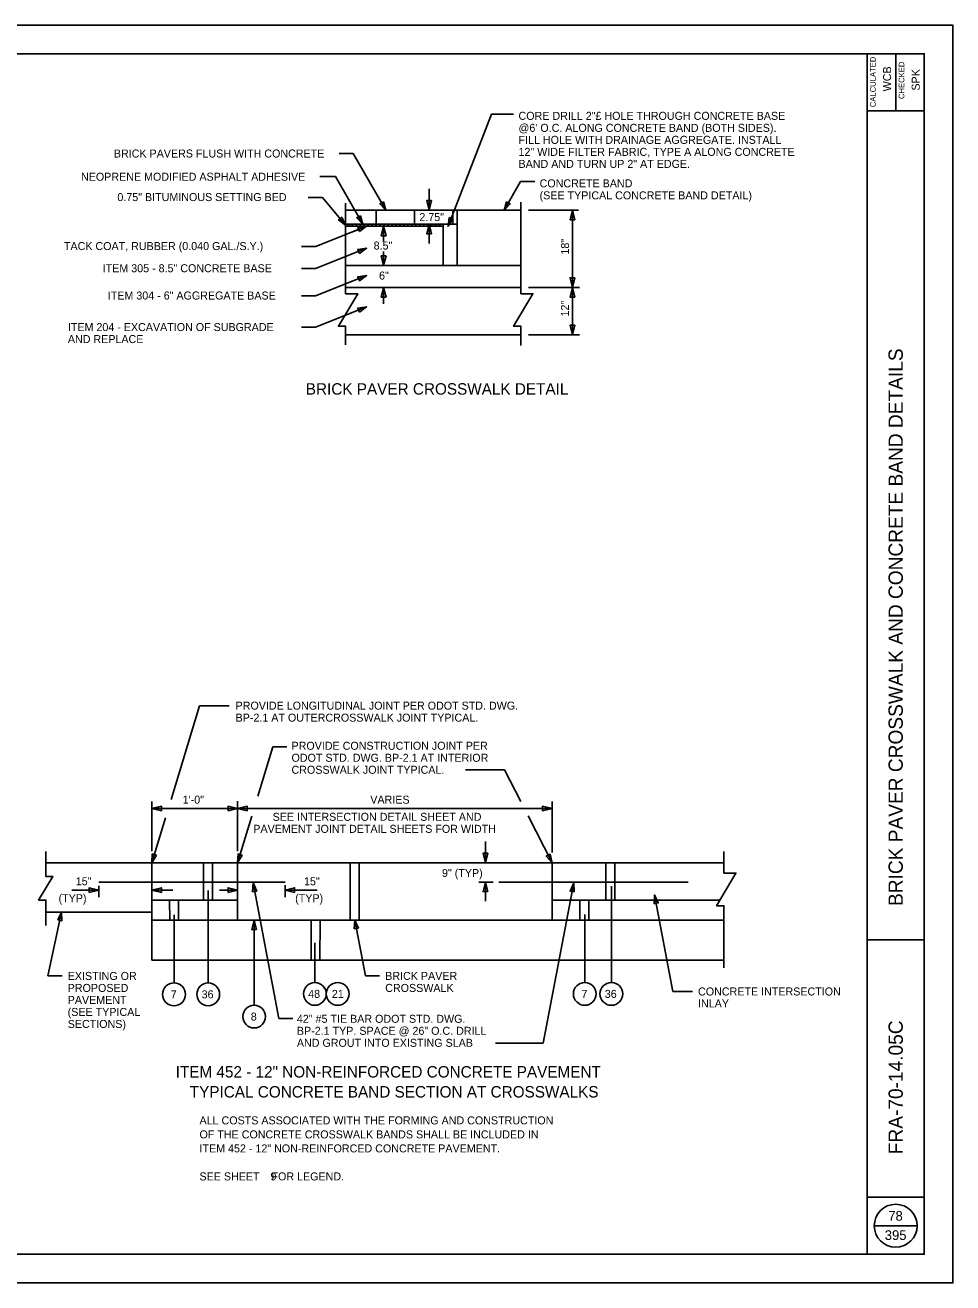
# Model space of a CAD drawing. Extents: x -848 to 1, y -1131 to -115.
# Drawn here: x -351.5 to -189.3, y -1130.8 to -910.8 of the extents above; entities that cross this region are included whole.
import ezdxf

# ---------------------------------------------------------------- set-up
doc = ezdxf.new("R2010")
doc.units = 0
for name, color, linetype in [('SH_Border', 7, 'Continuous'), ('SH_Cut_Line', 7, 'Continuous'), ('SH_Data', 7, 'Continuous'), ('SH_Text', 7, 'Continuous'), ('TX_X_5', 7, 'Continuous')]:
    doc.layers.add(name, color=color, linetype=linetype)

msp = doc.modelspace()

# ---------------------------------------------------------------- linework, layer by layer
at = {"layer": 'SH_Border'}
for p, q in [((-204.28, -1125.76), (-204.28, -915.76)), ((-199.28, -915.76), (-199.28, -925.76)), ((-204.28, -925.76), (-194.28, -925.76)), ((-204.28, -1070.76), (-194.28, -1070.76)), ((-204.28, -1115.76), (-194.28, -1115.76))]:
    msp.add_line(p, q, dxfattribs=at)
msp.add_lwpolyline([(-509.28, -915.76), (-194.28, -915.76), (-194.28, -1125.76), (-509.28, -1125.76)], close=True, dxfattribs=at)
at = {"layer": 'SH_Cut_Line'}
msp.add_lwpolyline([(-529.28, -1130.76), (-189.28, -1130.76), (-189.28, -910.76), (-529.28, -910.76)], close=True, dxfattribs=at)
at = {"layer": 'SH_Data'}
for p, q in [((-295.47, -943.13), (-264.82, -943.13)), ((-290.16, -943.13), (-290.16, -945.57)), ((-283.45, -943.13), (-283.45, -945.57)), ((-276.74, -943.13), (-276.74, -945.57)), ((-275.99, -943.13), (-275.99, -952.81)), ((-295.47, -945.57), (-275.99, -945.57)), ((-295.47, -945.92), (-295.47, -947.39)), ((-291.8, -945.92), (-293.05, -946.83)), ((-291.63, -945.92), (-291.8, -945.92)), ((-288.86, -945.92), (-289.55, -945.92)), ((-289.25, -947.6), (-288.83, -945.92)), ((-288.83, -945.92), (-288.86, -945.92)), ((-288.17, -945.92), (-288.83, -945.92)), ((-287.48, -945.92), (-288.17, -945.92)), ((-281.94, -945.92), (-282.63, -945.92)), ((-281.25, -945.92), (-281.94, -945.92)), ((-280.56, -945.92), (-281.25, -945.92)), ((-278.43, -945.92), (-278.59, -945.92)), ((-278.43, -948.01), (-278.43, -945.92)), ((-275.99, -952.81), (-275.99, -945.57)), ((-293.19, -946.48), (-295.47, -947.39)), ((-295.47, -947.39), (-293.19, -946.48)), ((-295.47, -947.39), (-295.47, -951.24)), ((-293.05, -946.83), (-293.19, -946.48)), ((-278.43, -949.37), (-278.43, -948.01)), ((-293.21, -950.33), (-293.35, -949.98)), ((-293.07, -950.68), (-293.21, -950.33)), ((-295.47, -951.24), (-295.47, -952.81)), ((-288.83, -952.81), (-289.25, -951.13)), ((-289.25, -951.13), (-288.83, -951.13)), ((-288.83, -951.13), (-288.41, -951.13)), ((-288.41, -951.13), (-288.83, -952.81)), ((-278.43, -952.81), (-278.43, -950.79)), ((-278.43, -950.79), (-278.43, -952.81)), ((-295.47, -952.81), (-264.82, -952.81)), ((-288.83, -952.81), (-295.47, -952.81)), ((-295.47, -952.81), (-295.47, -956.02)), ((-295.47, -952.81), (-288.83, -952.81)), ((-275.99, -952.81), (-288.83, -952.81)), ((-288.83, -952.81), (-278.43, -952.81)), ((-278.43, -952.81), (-275.99, -952.81)), ((-264.82, -952.81), (-275.99, -952.81)), ((-264.82, -956.63), (-264.82, -952.81)), ((-295.47, -956.02), (-295.47, -956.63)), ((-295.47, -956.63), (-264.82, -956.63)), ((-295.47, -964.93), (-264.82, -964.93)), ((-347.88, -1057.29), (-329.36, -1057.29)), ((-329.36, -1057.29), (-329.36, -1074.29)), ((-329.36, -1057.29), (-229.33, -1057.29)), ((-314.36, -1057.29), (-314.36, -1067.29)), ((-259.36, -1057.29), (-259.36, -1067.29)), ((-338.62, -1060.64), (-306.07, -1060.64)), ((-268.68, -1060.64), (-235.57, -1060.64)), ((-329.36, -1063.84), (-314.36, -1063.84)), ((-259.36, -1063.84), (-230.04, -1063.84)), ((-347.88, -1065.89), (-329.36, -1065.89)), ((-329.36, -1067.29), (-244.36, -1067.29)), ((-244.36, -1067.29), (-229.33, -1067.29)), ((-329.36, -1074.29), (-229.33, -1074.29)), ((-203.03, -1120.76), (-195.53, -1120.76))]:
    msp.add_line(p, q, dxfattribs=at)
for points in [[(-295.47, -941.91), (-295.47, -957.73), (-293.37, -957.73), (-296.75, -963.44), (-295.47, -963.44), (-295.47, -966.67)], [(-295.47, -941.91), (-295.47, -957.73), (-293.37, -957.73), (-296.75, -963.44), (-295.47, -963.44), (-295.47, -966.67)], [(-264.82, -941.7), (-264.82, -957.73), (-262.72, -957.73), (-266.09, -963.44), (-264.82, -963.44), (-264.82, -966.77)], [(-291.8, -945.92), (-292.32, -945.92), (-293.01, -945.92), (-293.7, -945.92), (-294.4, -945.92), (-295.09, -945.92), (-295.47, -945.92)], [(-293.19, -946.48), (-293.33, -946.13), (-291.8, -945.92)], [(-289.55, -945.92), (-290.24, -945.92), (-290.94, -945.92), (-291.63, -945.92)], [(-288.83, -945.92), (-288.41, -947.6), (-288.83, -947.6), (-289.25, -947.6)], [(-286.09, -945.92), (-286.79, -945.92), (-287.48, -945.92)], [(-284.02, -945.92), (-284.71, -945.92), (-285.4, -945.92), (-286.09, -945.92)], [(-282.63, -945.92), (-283.33, -945.92), (-284.02, -945.92)], [(-279.41, -945.92), (-279.61, -945.92), (-279.87, -945.92), (-280.56, -945.92)], [(-278.59, -945.92), (-278.84, -945.92), (-279.08, -945.92), (-279.18, -945.92), (-279.41, -945.92)], [(-275.99, -945.57), (-275.99, -945.57), (-275.99, -945.57), (-278.43, -945.57), (-278.43, -945.92)], [(-278.43, -945.92), (-278.43, -948.01), (-278.43, -949.37)], [(-293.35, -949.98), (-291.82, -949.77), (-293.07, -950.68)], [(-278.43, -950.79), (-278.43, -950.22), (-278.43, -949.37)], [(-278.43, -949.37), (-278.43, -950.22), (-278.43, -950.79)], [(-293.35, -954.77), (-291.82, -954.56), (-293.07, -955.47), (-293.21, -955.12), (-293.35, -954.77)], [(-295.47, -956.63), (-288.83, -956.63), (-264.82, -956.63)], [(-347.88, -1055.32), (-347.88, -1059.66), (-346.66, -1059.69), (-349.17, -1063.79), (-347.88, -1063.79), (-347.88, -1068.26)], [(-229.33, -1055.32), (-229.33, -1059.09), (-227.23, -1059.09), (-230.6, -1064.8), (-229.33, -1064.8), (-229.33, -1075.63)]]:
    msp.add_lwpolyline(points, dxfattribs=at)
msp.add_circle((-199.28, -1120.76), 3.75, dxfattribs=at)
at = {"layer": 'SH_Text'}
for p, q in [((-280.86, -939.37), (-280.86, -943.13)), ((-254.73, -943.13), (-263.49, -943.13)), ((-255.8, -943.13), (-255.8, -964.93)), ((-288.83, -945.92), (-288.83, -948.61)), ((-280.86, -945.57), (-280.86, -948.93)), ((-278.43, -945.57), (-278.43, -952.81)), ((-288.83, -950.36), (-288.83, -952.81)), ((-288.83, -956.63), (-288.83, -959.5)), ((-254.55, -956.63), (-263.49, -956.63)), ((-254.55, -964.93), (-263.49, -964.93)), ((-329.36, -1046.54), (-329.36, -1055.23)), ((-314.36, -1046.51), (-314.36, -1055.26)), ((-314.36, -1046.54), (-314.36, -1055.26)), ((-259.36, -1046.54), (-259.36, -1055.48)), ((-259.36, -1047.8), (-329.36, -1047.8)), ((-271.01, -1053.53), (-271.01, -1057.29)), ((-318.75, -1057.29), (-320.32, -1057.29)), ((-320.32, -1057.29), (-320.32, -1063.84)), ((-318.76, -1063.84), (-318.75, -1057.29)), ((-293.1, -1057.29), (-294.68, -1057.29)), ((-294.68, -1057.29), (-294.67, -1067.29)), ((-293.11, -1067.29), (-293.1, -1057.29)), ((-248.38, -1057.29), (-249.96, -1057.29)), ((-249.96, -1057.29), (-249.95, -1063.84)), ((-248.39, -1063.84), (-248.38, -1057.29)), ((-338.62, -1062.08), (-343.34, -1062.08)), ((-338.62, -1061.33), (-338.62, -1063.32)), ((-325.72, -1062.08), (-329.36, -1062.08)), ((-319.51, -1078.3), (-319.51, -1062.14)), ((-314.36, -1062.08), (-317.51, -1062.08)), ((-306.07, -1061.2), (-306.07, -1063.32)), ((-300.44, -1062.08), (-306.07, -1062.08)), ((-269.69, -1060.64), (-272.16, -1060.64)), ((-271.01, -1060.64), (-271.01, -1064)), ((-249, -1078.22), (-249, -1061.38)), ((-324.68, -1063.84), (-326.25, -1063.84)), ((-326.25, -1063.84), (-326.24, -1067.29)), ((-324.68, -1067.29), (-324.68, -1063.84)), ((-320.32, -1063.84), (-318.76, -1063.84)), ((-252.92, -1063.84), (-254.49, -1063.84)), ((-254.49, -1063.84), (-254.49, -1067.29)), ((-252.92, -1067.29), (-252.92, -1063.84)), ((-249.95, -1063.84), (-248.39, -1063.84)), ((-325.49, -1078.3), (-325.49, -1066.38)), ((-253.66, -1078.22), (-253.66, -1066.31)), ((-326.24, -1067.29), (-324.68, -1067.29)), ((-311.47, -1082.19), (-311.47, -1067.29)), ((-299.95, -1067.29), (-301.53, -1067.29)), ((-301.53, -1067.29), (-301.52, -1074.29)), ((-299.96, -1074.29), (-299.95, -1067.29)), ((-294.67, -1067.29), (-293.11, -1067.29)), ((-254.49, -1067.29), (-252.92, -1067.29)), ((-300.85, -1078.22), (-300.85, -1071.28)), ((-301.52, -1074.29), (-299.96, -1074.29))]:
    msp.add_line(p, q, dxfattribs=at)
for points in [[(-280.44, -941.45), (-280.86, -943.13), (-281.28, -941.45)], [(-255.38, -944.81), (-255.8, -943.13), (-256.22, -944.81)], [(-288.41, -947.6), (-288.83, -945.92), (-289.25, -947.6)], [(-280.44, -947.25), (-280.86, -945.57), (-281.28, -947.25)], [(-288.41, -951.13), (-288.83, -952.81), (-289.25, -951.13)], [(-288.41, -958.31), (-288.83, -956.63), (-289.25, -958.31)], [(-255.38, -954.95), (-255.8, -956.63), (-256.22, -954.95)], [(-255.38, -958.31), (-255.8, -956.63), (-256.22, -958.31)], [(-255.38, -963.25), (-255.8, -964.93), (-256.22, -963.25)], [(-327.68, -1048.22), (-329.36, -1047.8), (-327.68, -1047.38)], [(-316.04, -1048.22), (-314.36, -1047.8), (-316.04, -1047.38)], [(-312.68, -1048.22), (-314.36, -1047.8), (-312.68, -1047.38)], [(-261.04, -1048.22), (-259.36, -1047.8), (-261.04, -1047.38)], [(-270.59, -1055.61), (-271.01, -1057.29), (-271.43, -1055.61)], [(-340.3, -1062.5), (-338.62, -1062.08), (-340.3, -1061.66)], [(-327.68, -1062.5), (-329.36, -1062.08), (-327.68, -1061.66)], [(-316.04, -1062.5), (-314.36, -1062.08), (-316.04, -1061.66)], [(-304.39, -1062.5), (-306.07, -1062.08), (-304.39, -1061.66)], [(-270.59, -1062.32), (-271.01, -1060.64), (-271.43, -1062.32)], [(-311.05, -1068.97), (-311.47, -1067.29), (-311.89, -1068.97)]]:
    msp.add_lwpolyline(points, close=True, dxfattribs=at)
for centre in [(-325.49, -1080.29), (-319.51, -1080.29), (-300.85, -1080.21), (-296.87, -1080.21), (-253.66, -1080.21), (-249, -1080.21), (-311.47, -1084.18)]:
    msp.add_circle(centre, 1.99, dxfattribs=at)
at = {"layer": 'TX_X_5'}
for p, q in [((-277.56, -945.92), (-269.96, -926.32)), ((-266.1, -926.32), (-269.96, -926.32)), ((-296.61, -933.21), (-294.13, -933.21)), ((-288.44, -943.13), (-294.13, -933.21)), ((-299.96, -937.26), (-297.24, -937.26)), ((-292.47, -945.57), (-297.24, -937.26)), ((-267.75, -943.13), (-264.88, -938.12)), ((-262.41, -938.12), (-264.88, -938.12)), ((-302, -940.89), (-299.5, -940.89)), ((-295.47, -945.74), (-299.5, -940.89)), ((-291.8, -945.92), (-300.7, -949.49)), ((-295.09, -945.92), (-294.88, -945.57)), ((-294.4, -945.92), (-294.19, -945.57)), ((-293.7, -945.92), (-293.5, -945.57)), ((-293.01, -945.92), (-292.81, -945.57)), ((-292.32, -945.92), (-292.12, -945.57)), ((-291.63, -945.92), (-291.43, -945.57)), ((-290.94, -945.92), (-290.73, -945.57)), ((-290.24, -945.92), (-290.04, -945.57)), ((-289.55, -945.92), (-289.35, -945.57)), ((-288.86, -945.92), (-288.66, -945.57)), ((-288.17, -945.92), (-287.97, -945.57)), ((-287.48, -945.92), (-287.28, -945.57)), ((-286.79, -945.92), (-286.58, -945.57)), ((-286.09, -945.92), (-285.89, -945.57)), ((-285.4, -945.92), (-285.2, -945.57)), ((-284.71, -945.92), (-284.51, -945.57)), ((-284.02, -945.92), (-283.82, -945.57)), ((-283.33, -945.92), (-283.12, -945.57)), ((-282.63, -945.92), (-282.43, -945.57)), ((-281.94, -945.92), (-281.74, -945.57)), ((-281.25, -945.92), (-281.05, -945.57)), ((-280.56, -945.92), (-280.36, -945.57)), ((-279.87, -945.92), (-279.67, -945.57)), ((-279.18, -945.92), (-278.97, -945.57)), ((-303.17, -949.49), (-300.7, -949.49)), ((-291.82, -949.77), (-300.72, -953.34)), ((-303.19, -953.34), (-300.72, -953.34)), ((-291.82, -954.56), (-300.72, -958.12)), ((-303.19, -958.12), (-300.72, -958.12)), ((-291.82, -960.04), (-300.72, -963.6)), ((-303.19, -963.6), (-300.72, -963.6)), ((-326, -1046.18), (-321.04, -1029.8)), ((-315.82, -1029.8), (-321.04, -1029.8)), ((-310.84, -1045.64), (-308.22, -1037)), ((-305.75, -1037), (-308.22, -1037)), ((-267.67, -1041), (-274.5, -1041)), ((-264.84, -1046.54), (-267.67, -1041)), ((-314.36, -1057.29), (-311.9, -1049.14)), ((-259.36, -1057.29), (-263.57, -1049.05)), ((-329.36, -1057.29), (-326.98, -1049.43)), ((-311.67, -1060.81), (-307.15, -1084.5)), ((-255.57, -1060.81), (-260.91, -1088.83)), ((-241.45, -1062.91), (-238.23, -1079.79)), ((-345.14, -1065.89), (-347.54, -1077.07)), ((-293.88, -1067.29), (-292.01, -1077.07)), ((-345.07, -1077.07), (-347.54, -1077.07)), ((-289.54, -1077.07), (-292.01, -1077.07)), ((-234.83, -1079.79), (-238.23, -1079.79)), ((-304.68, -1084.5), (-307.15, -1084.5)), ((-260.91, -1088.83), (-269.27, -1088.83))]:
    msp.add_line(p, q, dxfattribs=at)
for points in [[(-288.86, -941.64), (-288.44, -943.13), (-289.51, -942.02)], [(-267.33, -941.64), (-267.75, -943.13), (-266.68, -942.02)], [(-296.14, -944.34), (-295.47, -945.74), (-296.72, -944.82)], [(-292.89, -944.09), (-292.47, -945.57), (-293.54, -944.46)], [(-293.05, -946.83), (-291.8, -945.92), (-293.33, -946.13)], [(-277.37, -944.39), (-277.56, -945.92), (-276.67, -944.66)], [(-293.07, -950.68), (-291.82, -949.77), (-293.35, -949.98)], [(-293.07, -955.47), (-291.82, -954.56), (-293.35, -954.77)], [(-293.07, -960.95), (-291.82, -960.04), (-293.35, -960.25)], [(-328.57, -1055.96), (-329.36, -1057.29), (-329.29, -1055.74)], [(-313.57, -1055.96), (-314.36, -1057.29), (-314.29, -1055.74)], [(-259.71, -1055.78), (-259.36, -1057.29), (-260.38, -1056.12)], [(-311.76, -1062.36), (-311.67, -1060.81), (-311.02, -1062.22)], [(-255.48, -1062.36), (-255.57, -1060.81), (-256.22, -1062.22)], [(-241.54, -1064.45), (-241.45, -1062.91), (-240.8, -1064.31)], [(-345.83, -1067.27), (-345.14, -1065.89), (-345.09, -1067.43)], [(-293.97, -1068.83), (-293.88, -1067.29), (-293.23, -1068.69)]]:
    msp.add_lwpolyline(points, close=True, dxfattribs=at)

# ---------------------------------------------------------------- texts
at = {"layer": 'SH_Data'}
for s, height, p in [('CALCULATED', 1, (-202.76, -925.11)), ('CHECKED', 1, (-197.76, -923.68)), ('WCB', 1.4, (-200.08, -922.33)), ('SPK', 1.4, (-195.08, -922.2)), ('BRICK PAVER CROSSWALK AND CONCRETE BAND DETAILS', 2.5, (-198.03, -1064.83)), ('FRA-70-14.05C', 2.5, (-198.03, -1108.26))]:
    msp.add_text(s, height=height, rotation=90, dxfattribs=at).set_placement(p)
for s, p in [('78', (-200.57, -1119.89)), ('395', (-201.18, -1123.26))]:
    msp.add_text(s, height=1.7, dxfattribs=at).set_placement(p)
at = {"layer": 'SH_Text'}
for s, rotation, p in [('2.75"', 360, (-282.58, -945.03)), ('8.5"', 360, (-290.57, -950.01)), ('18"', 90, (-256.41, -950.89)), ('6"', 360, (-289.63, -955.26)), ('12"', 90, (-256.41, -961.72)), ('1\'-0"', 360, (-323.97, -1046.94)), ('VARIES', 360, (-291.16, -1046.94)), ('SEE INTERSECTION DETAIL SHEET AND', 360, (-308.24, -1049.94)), ('PAVEMENT JOINT DETAIL SHEETS FOR WIDTH', 360, (-311.62, -1052.04)), ('15"', 360, (-342.67, -1061.21)), ('15"', 360, (-302.75, -1061.21)), ('9" (TYP)', 360, (-278.62, -1059.76)), ('(TYP)', 360, (-345.68, -1064.17)), ('(TYP)', 360, (-304.3, -1064.17))]:
    msp.add_text(s, height=1.4, rotation=rotation, dxfattribs=at).set_placement(p)
for s, height, p in [('BRICK PAVER CROSSWALK DETAIL', 2, (-302.44, -975.39)), ('7', 1.4, (-326.06, -1080.99)), ('36', 1.4, (-320.66, -1080.99)), ('48', 1.4, (-302.03, -1080.91)), ('21', 1.4, (-297.88, -1080.91)), ('7', 1.4, (-254.23, -1080.91)), ('36', 1.4, (-250.15, -1080.91)), ('8', 1.4, (-312.06, -1084.88)), ('ITEM 452 - 12" NON-REINFORCED CONCRETE PAVEMENT', 2, (-325.2, -1094.84)), ('TYPICAL CONCRETE BAND SECTION AT CROSSWALKS', 2, (-322.73, -1098.34)), ('ALL COSTS ASSOCIATED WITH THE FORMING AND CONSTRUCTION ', 1.4, (-321.03, -1103.04)), ('OF THE CONCRETE CROSSWALK BANDS SHALL BE INCLUDED IN ', 1.4, (-321.03, -1105.49)), ('ITEM 452 - 12" NON-REINFORCED CONCRETE PAVEMENT.', 1.4, (-321.03, -1107.94)), ('SEE SHEET    FOR LEGEND.', 1.4, (-321.03, -1112.84)), ('9', 1.4, (-308.62, -1112.84))]:
    msp.add_text(s, height=height, dxfattribs=at).set_placement(p)
at = {"layer": 'TX_X_5'}
for s, p in [('CORE DRILL 2"£ HOLE THROUGH CONCRETE BASE ', (-265.24, -927.32)), ("@6' O.C. ALONG CONCRETE BAND (BOTH SIDES).", (-265.24, -929.42)), ('FILL HOLE WITH DRAINAGE AGGREGATE. INSTALL ', (-265.24, -931.52)), ('BRICK PAVERS FLUSH WITH CONCRETE', (-336.01, -933.91)), ('12" WIDE FILTER FABRIC, TYPE A ALONG CONCRETE', (-265.24, -933.62)), ('BAND AND TURN UP 2" AT EDGE.', (-265.24, -935.72)), ('NEOPRENE MODIFIED ASPHALT ADHESIVE', (-341.75, -937.97)), ('CONCRETE BAND ', (-261.55, -939.13)), ('0.75" BITUMINOUS SETTING BED', (-335.39, -941.53)), ('(SEE TYPICAL CONCRETE BAND DETAIL)', (-261.55, -941.23)), ('TACK COAT, RUBBER (0.040 GAL./S.Y.)', (-344.74, -950.1)), ('ITEM 305 - 8.5" CONCRETE BASE', (-337.96, -953.98)), ('ITEM 304 - 6" AGGREGATE BASE', (-337.07, -958.75)), ('ITEM 204 - EXCAVATION OF SUBGRADE ', (-344.05, -964.27)), ('AND REPLACE', (-344.05, -966.37)), ('PROVIDE LONGITUDINAL JOINT PER ODOT STD. DWG. ', (-314.72, -1030.49)), ('BP-2.1 AT OUTERCROSSWALK JOINT TYPICAL.', (-314.72, -1032.59)), ('PROVIDE CONSTRUCTION JOINT PER', (-304.94, -1037.51)), ('ODOT STD. DWG. BP-2.1 AT INTERIOR', (-304.94, -1039.61)), ('CROSSWALK JOINT TYPICAL.', (-304.94, -1041.71)), ('EXISTING OR ', (-344.08, -1077.77)), ('BRICK PAVER', (-288.55, -1077.77)), ('PROPOSED ', (-344.08, -1079.87)), ('CROSSWALK', (-288.55, -1079.87)), ('CONCRETE INTERSECTION ', (-233.84, -1080.49)), ('PAVEMENT', (-344.08, -1081.97)), ('INLAY', (-233.84, -1082.59)), ('(SEE TYPICAL', (-344.08, -1084.07)), ('42" #5 TIE BAR ODOT STD. DWG.', (-304, -1085.27)), ('SECTIONS)', (-344.08, -1086.17)), ('BP-2.1 TYP. SPACE @ 26" O.C. DRILL', (-304, -1087.37)), ('AND GROUT INTO EXISTING SLAB', (-304, -1089.47))]:
    msp.add_text(s, height=1.4, dxfattribs=at).set_placement(p)

doc.saveas('drawing.dxf')
